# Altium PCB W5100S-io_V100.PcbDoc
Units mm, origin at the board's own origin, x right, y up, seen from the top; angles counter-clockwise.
Board outline 20 x 24 mm, 4 copper layers (Top Layer, Internal Plane 1, Internal Plane 2, Bottom Layer), stack 0.844 mm thick; 38 components, 31 nets, 160 pads, 49 vias.
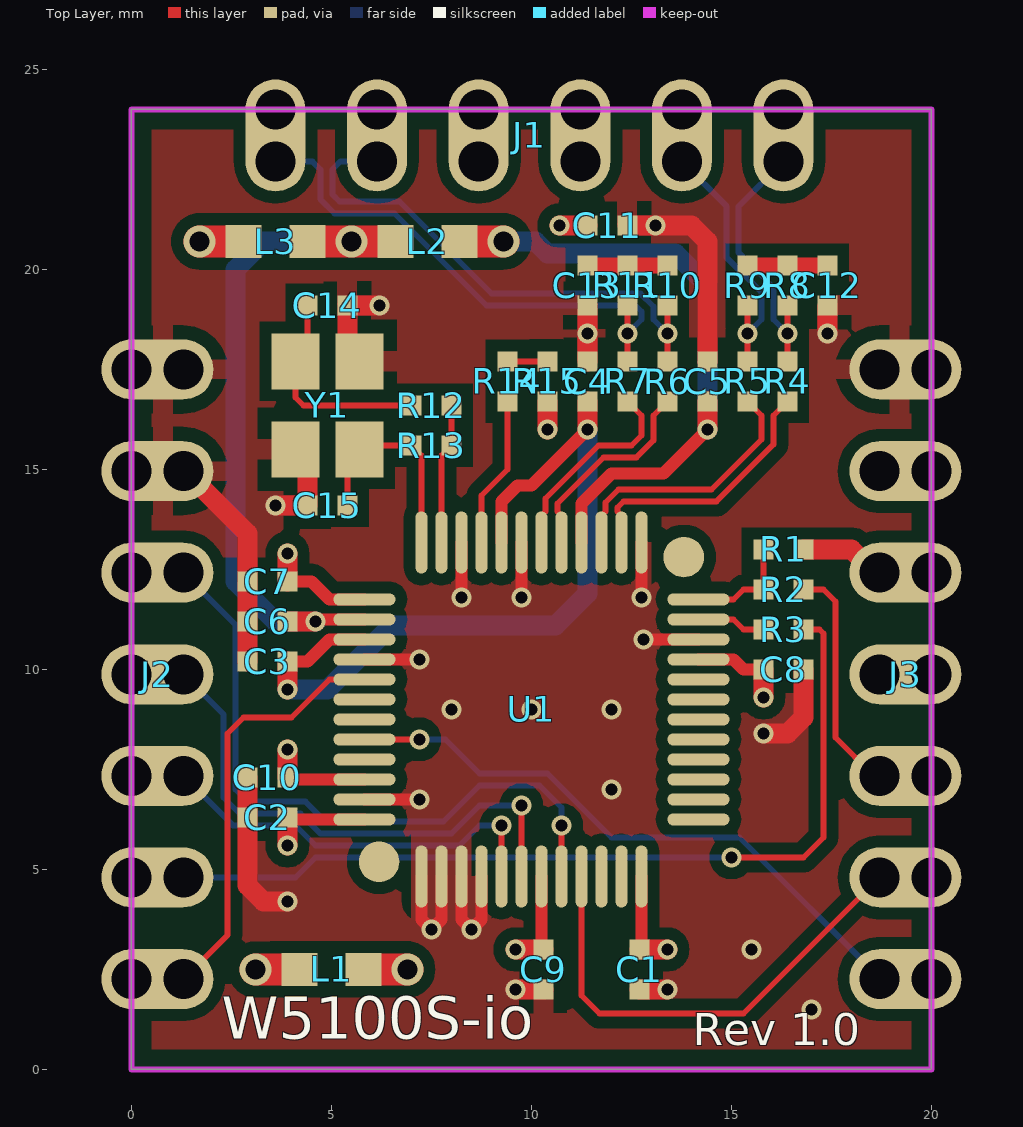
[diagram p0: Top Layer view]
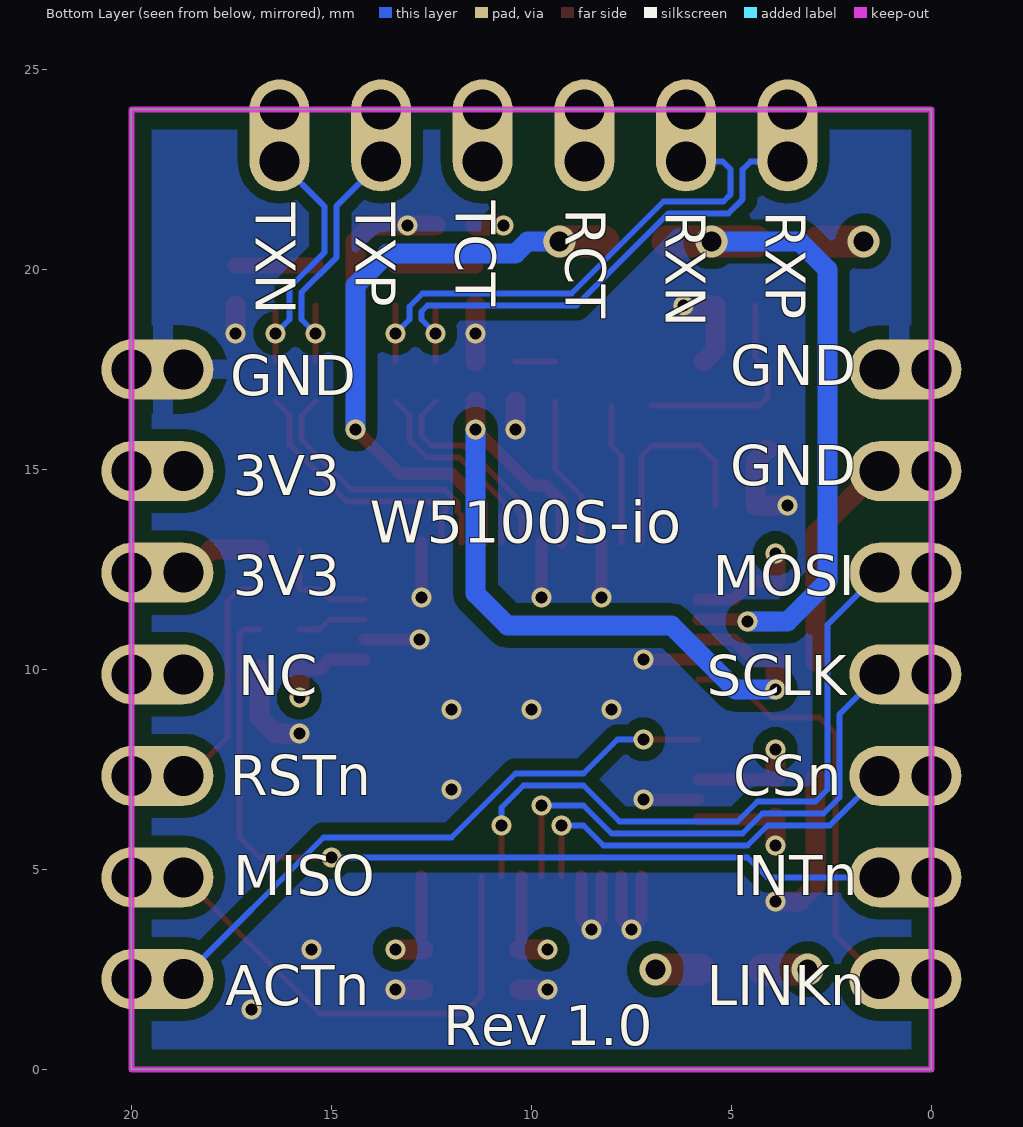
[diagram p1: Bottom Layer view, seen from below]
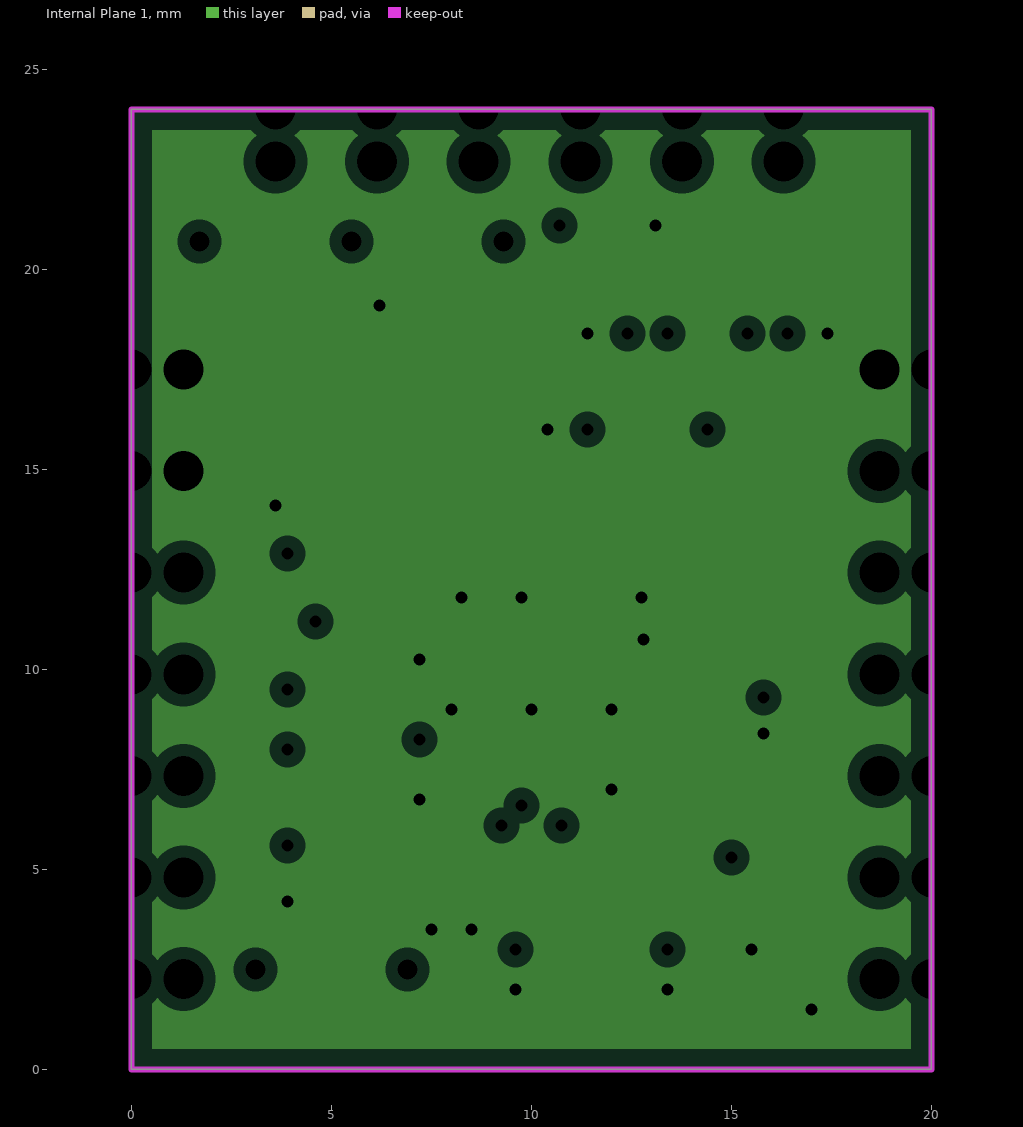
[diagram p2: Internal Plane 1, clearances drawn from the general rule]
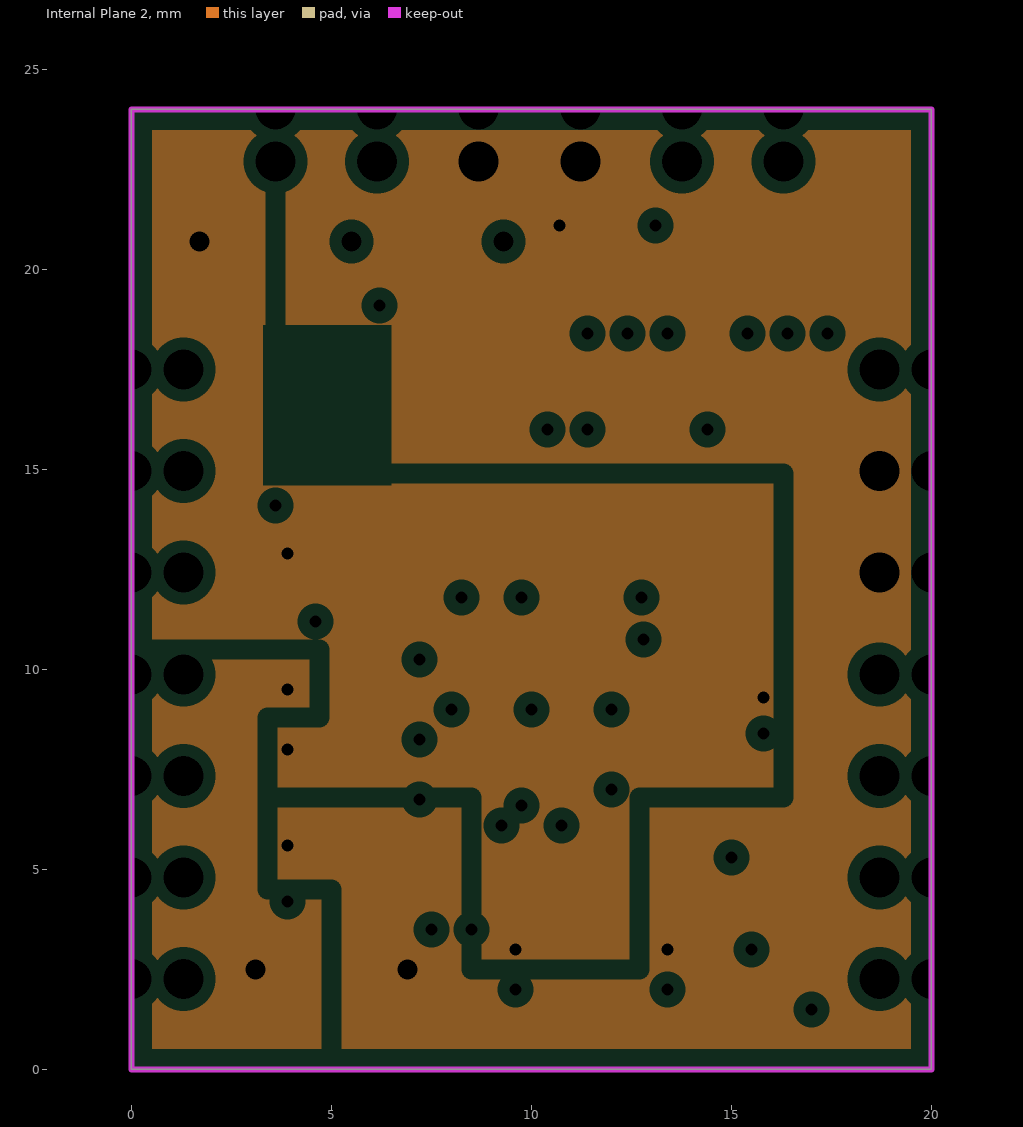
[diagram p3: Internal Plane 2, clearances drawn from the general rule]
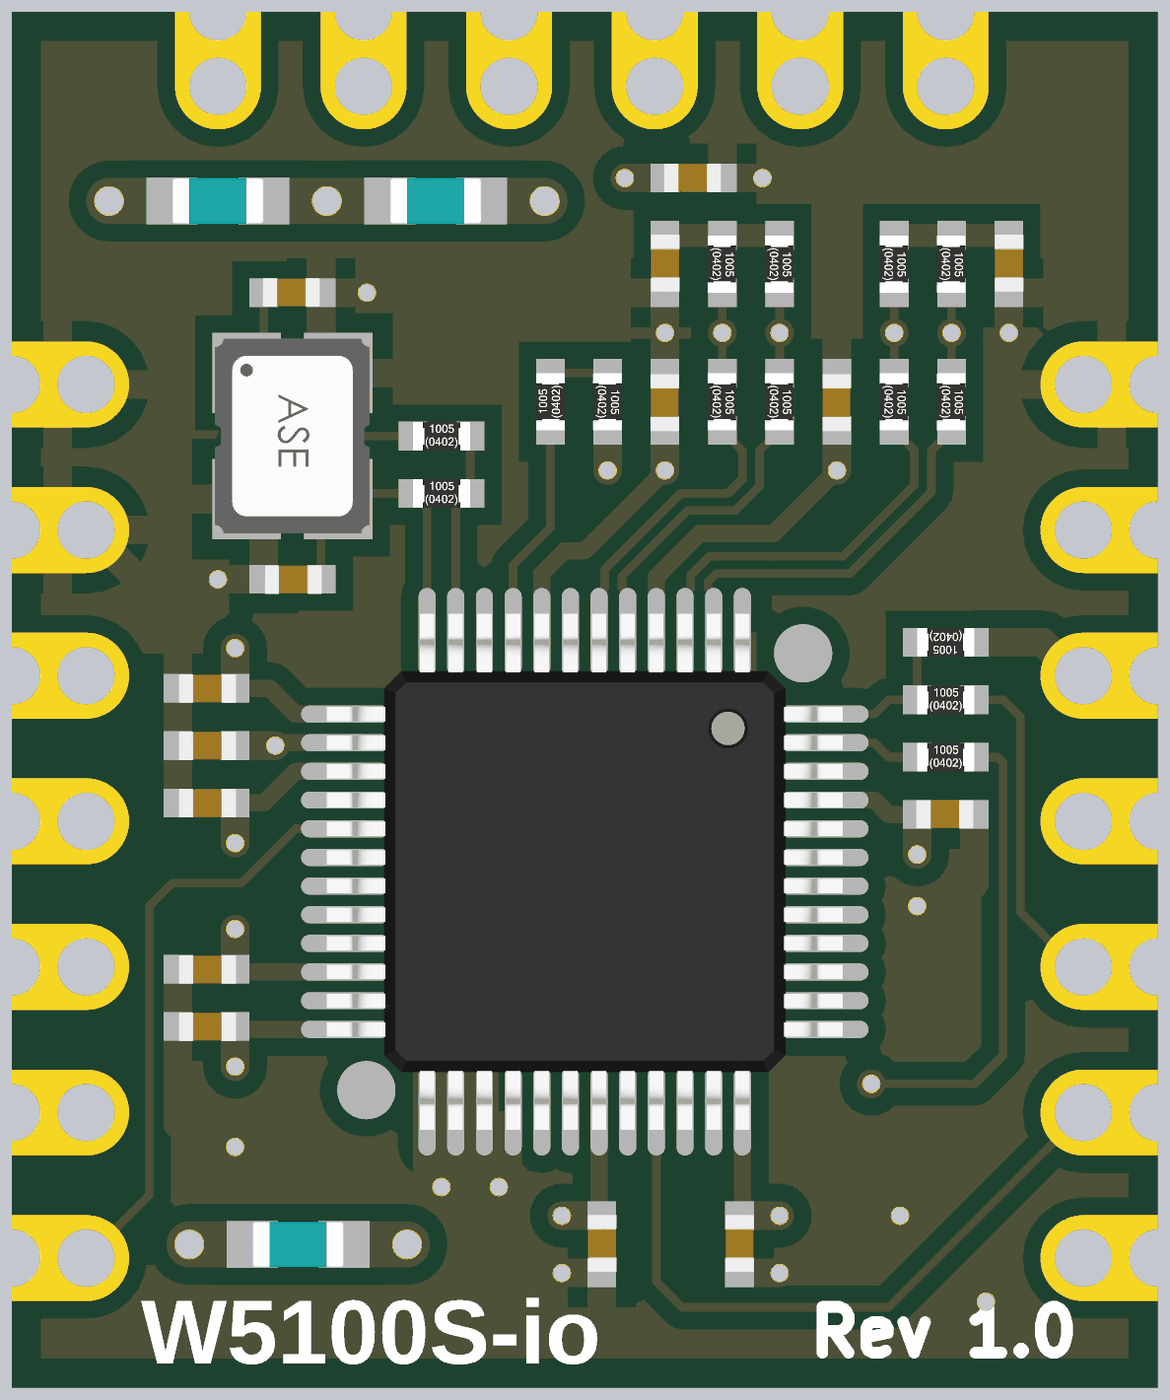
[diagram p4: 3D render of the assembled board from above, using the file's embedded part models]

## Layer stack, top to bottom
Top Solder: solder mask 0.0102, Solder Resist, Dk 3.5
Top Layer: signal copper 0.0356
Dielectric1: core 0.32, FR-4, Dk 4.8
Internal Plane 1: plane copper 0.0356, net GND
Dielectric 6: prepreg 0.127, Dk 4.2
Internal Plane 2: plane copper 0.036, net 3V3
Dielectric5: core 0.254, FR-4, Dk 4.2
Bottom Layer: signal copper 0.0356
Bottom Solder: solder mask 0.0102, Solder Resist, Dk 3.5

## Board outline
0,0 0,24 20,24 20,0

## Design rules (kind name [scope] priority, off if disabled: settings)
BoardOutlineClearance [All] p1: gap=0.5 ignorepadtopadclearanceinfootprint=FALSE
Clearance [All] p1: gap=0.15 ignorepadtopadclearanceinfootprint=FALSE except(0: Arc-Hole Track-Hole SMDPad-Hole THPad-Hole Via-Hole Fill-Hole Region-Hole Text-Hole; 0.3: Arc-Poly Track-Poly SMDPad-Poly THPad-Poly Via-Poly Fill-Poly Poly-Poly Poly-Region Poly-Text Poly-Hole)
DiffPairsRouting [All] p1: maxlimit=0.15 minlimit=0.15 mostfreqgap=0.15 toplayer_minwidth=0.15 toplayer_maxwidth=0.15 toplayer_prefwidth=0.15 bottomlayer_minwidth=0.15 bottomlayer_maxwidth=0.15 bottomlayer_prefwidth=0.15 maxuncoupledlength=15.24
HoleSize [All] p1: absolutevalues=TRUE maxlimit=4.064 minlimit=0.025 maxpercent=80.000 minpercent=20.000
PlaneClearance [All] p1: clearance=0.3
PlaneConnect [All] p1: planeconnectstyle=Direct reliefexpansion=0.508 reliefentries=4 reliefconductorwidth=0.254 reliefairgap=0.254
PolygonConnect [All] p1: thpad.connectstyle=Relief thpad.reliefconductorwidth=0.5 thpad.reliefentries=4 thpad.polygonreliefangle="90 Angle" thpad.airgapwidth=0.35 smdpad.connectstyle=Relief smdpad.reliefconductorwidth=0.5 smdpad.reliefentries=4 smdpad.polygonreliefangle="90 Angle" smdpad.airgapwidth=0.35 via.connectstyle=Direct via.reliefconductorwidth=0.254 via.reliefentries=4 via.polygonreliefangle="90 Angle" via.airgapwidth=0.254
RoutingVias [All] p1: holewidth=0.3 width=0.5 viastyle="Through Hole" minholewidth=0.3 minwidth=0.5 maxholewidth=0.5 maxwidth=0.8
SolderMaskExpansion [All] p1: expansion=0 istentingtop=FALSE
Width [All] p1: maxlimit=2.54 minlimit=0.102 preferedwidth=0.152
26 further rules are at their usual default settings.

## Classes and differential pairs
differential pair NewDifferentialPair4: +TX_N -TX_P
differential pair NewDifferentialPair3: +RX_N -RX_P
differential pair NewDifferentialPair2: +NetR5_2 -NetR4_2
differential pair NewDifferentialPair1: +NetR7_2 -NetR6_2

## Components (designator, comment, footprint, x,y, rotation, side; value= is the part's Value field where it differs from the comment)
C1 "0.1uF" CAP-0402 12.7,2.5 r90 top
C2 "0.1uF" CAP-0402 3.4,6.3 r0 top
C3 "0.1uF" CAP-0402 3.4,10.2 r0 top
C4 "0.1uF" CAP-0402 11.4,17.2 r270 top
C5 "0.1uF" CAP-0402 14.4,17.2 r270 top
C6 "1uF" CAP-0402 3.4,11.2 r0 top
C7 "0.1uF" CAP-0402 3.4,12.2 r0 top
C8 "0.1uF" CAP-0402 16.3,10 r180 top
C9 "0.1uF" CAP-0402 10.3,2.5 r90 top
C10 "0.1uF" CAP-0402 3.4,7.3 r0 top
C11 "0.1uF" CAP-0402 11.9,21.1 r180 top
C12 "0.1uF" CAP-0402 17.4,19.6 r90 top
C13 "0.1uF" CAP-0402 11.4,19.6 r90 top
C14 "18pF" CAP-0402 4.9,19.1 r180 top
C15 "18pF" CAP-0402 4.9,14.1 r0 top
J1 "2.54mm 1x6 Pin Header DIP" IDC-1X6(WI510IO) 16.3,22.7 r180 top
J2 "2.54mm 1x7 Pin Header DIP" IDC-1X7(WI510IO) 1.3,17.5 r270 top
J3 "2.54mm 1x7 Pin Header DIP" IDC-1X7(WI510IO) 20,17.5 r270 top
L1 "HH-1M1608-121JT" IND-0603 5,2.5 r180 top
L2 "HH-1M1608-121JT" IND-0603 7.4,20.7 r180 top
L3 "HH-1M1608-121JT" IND-0603 3.6,20.7 r180 top
R1 "4.7K" RES-0402 16.3,13 r180 top
R2 "0R" RES-0402 16.3,12 r0 top
R3 "0R" RES-0402 16.3,11 r0 top
R4 "3.3R" RES-0402 16.4,17.2 r270 top
R5 "3.3R" RES-0402 15.4,17.2 r270 top
R6 "3.3R" RES-0402 13.4,17.2 r270 top
R7 "3.3R" RES-0402 12.4,17.2 r270 top
R8 "49.9R" RES-0402 16.4,19.6 r270 top
R9 "49.9R" RES-0402 15.4,19.6 r270 top
R10 "49.9R" RES-0402 13.4,19.6 r270 top
R11 "49.9R" RES-0402 12.4,19.6 r270 top
R12 "0R" RES-0402 7.5,16.6 r0 top
R13 "1M" RES-0402 7.5,15.6 r0 top
R14 "12K/1%" RES-0402 9.4,17.2 r90 top
R15 "300R" RES-0402 10.4,17.2 r270 top
U1 "W5100S" LQFP48(0.5/9.0) 10,9 r270 top
Y1 "25MHz" OSC-82J0626 4.9,16.6 r270 top

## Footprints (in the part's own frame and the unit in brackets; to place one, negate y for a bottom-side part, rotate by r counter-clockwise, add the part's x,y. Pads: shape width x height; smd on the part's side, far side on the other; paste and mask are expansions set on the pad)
CAP-0402 [mm]
  rect 0.5x0.5 smd: 1(-0.5,0) 2(0.5,0)
  body extent -0.48,-0.25 0.52,0.25, height 0.6
IDC-1X6(WI510IO) [mm]
  oval 1.5x2.5 hole 1 copper offset 0,-0.5: 1(0,0) 2(2.54,0) 3(5.08,0) 4(7.62,0) 5(10.16,0) 6(12.7,0)
  oval 1.5x2.5 hole 1 copper offset 0,0.5: 1(0,-1.3) 2(2.54,-1.3) 3(5.08,-1.3) 4(7.62,-1.3) 5(10.16,-1.3) 6(12.7,-1.3)
IDC-1X7(WI510IO) [mm]
  oval 1.5x2.5 hole 1 copper offset 0,-0.5: 1(0,0) 2(2.54,0) 3(5.08,0) 4(7.62,0) 5(10.16,0) 6(12.7,0) 7(15.24,0)
  oval 1.5x2.5 hole 1 copper offset 0,0.5: 1(0,-1.3) 2(2.54,-1.3) 3(5.08,-1.3) 4(7.62,-1.3) 5(10.16,-1.3) 6(12.7,-1.3) 7(15.24,-1.3)
IND-0603 [mm] "Inductor 0603(1608)"
  rect 0.89x0.82 smd: 1(-0.8,0) 2(0.8,0)
  body extent -0.8,-0.4 0.8,0.4, height 0.95
LQFP48(0.5/9.0) [mm]
  round 1.016 smd: 0(-3.81,3.81) 0(3.81,-3.81)
  oval 1.55x0.3 smd: 1(-4.175,2.75) 2(-4.175,2.25) 3(-4.175,1.75) 4(-4.175,1.25) 5(-4.175,0.75) 6(-4.175,0.25) 7(-4.175,-0.25) 8(-4.175,-0.75) 9(-4.175,-1.25) 10(-4.175,-1.75) 11(-4.175,-2.25) 12(-4.175,-2.75) 25(4.175,-2.75) 26(4.175,-2.25) 27(4.175,-1.75) 28(4.175,-1.25) 29(4.175,-0.75) 30(4.175,-0.25) 31(4.175,0.25) 32(4.175,0.75) 33(4.175,1.25) 34(4.175,1.75) 35(4.175,2.25) 36(4.175,2.75)
  oval 0.3x1.55 smd: 13(-2.75,-4.175) 14(-2.25,-4.175) 15(-1.75,-4.175) 16(-1.25,-4.175) 17(-0.75,-4.175) 18(-0.25,-4.175) 19(0.25,-4.175) 20(0.75,-4.175) 21(1.25,-4.175) 22(1.75,-4.175) 23(2.25,-4.175) 24(2.75,-4.175) 37(2.75,4.175) 38(2.25,4.175) 39(1.75,4.175) 40(1.25,4.175) 41(0.75,4.175) 42(0.25,4.175) 43(-0.25,4.175) 44(-0.75,4.175) 45(-1.25,4.175) 46(-1.75,4.175) 47(-2.25,4.175) 48(-2.75,4.175)
  body extent -4.5,-4.5 4.5,4.5, height 1.5
OSC-82J0626 [mm]
  rect 1.4x1.2 smd: 1(-1.1,-0.8) 2(1.1,-0.8) 3(1.1,0.8) 4(-1.1,0.8)
  body extent -1.7,-1.35 1.7,1.35, height 1.06
RES-0402 [mm]
  rect 0.5x0.5 smd: 1(-0.5,0) 2(0.5,0)
  body extent -0.5,-0.25 0.5,0.25, height 0.35

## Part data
C1 C2 C3 C4 C5 C6 C7 C8 C9 C10 C11 C12 C13 C14 C15: library part CAP-0402, "Ceramic CAP 0402(1005)"
L1 L2 L3: library part IND-0603, "Inductor 0603(1608)"
R1 R2 R3 R4 R5 R6 R7 R8 R9 R10 R11 R12 R13 R14 R15: library part RES-0402, "RES-0402"
U1: "WIZnet Hardwired TCP/IP Chip"
Y1: library part OSC-82J0626-25MHz, "X-tal 25MHz,3.2x2.5 SMD, CL=18pF"

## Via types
v1: diameter 0.5, hole 0.3, Top Layer to Bottom Layer, tented both sides, 44 vias
v2: diameter 0.8, hole 0.5, Top Layer to Bottom Layer, tented both sides, 5 vias

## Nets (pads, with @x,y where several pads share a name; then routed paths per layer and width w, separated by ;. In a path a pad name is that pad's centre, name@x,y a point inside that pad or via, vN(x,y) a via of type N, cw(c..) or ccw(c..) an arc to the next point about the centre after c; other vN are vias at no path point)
1V2A: C5.2 L2.1 U1.4 | length 15.8
  Top Layer w0.3: U1.4 11.25,14.15 12,14.9 13.3,14.9 v1(14.4,16)
  Top Layer w0.5: v1(14.4,16) C5.2
  Top Layer w0.8: L2.1 v2(9.3,20.7)
  Bottom Layer w0.5: v2(9.3,20.7) 10.1,20.7 10.4,20.4 13.6,20.4 14.4,19.6 v1(14.4,16)
1V2D: C7.2 C8.2 C9.2 C10.2 L3.2 U1.13 U1.22 U1.31 U1.45 | length 11.5
  Top Layer w0.3: C10.2 3.95,7.25 U1.22 ; C7.2 4.5,12.2 4.95,11.75 U1.13 ; U1.31 10.25,3.05 C9.2 ; U1.45 15.05,10.25 15.3,10 C8.2
  Top Layer w0.5: C10.2 v1(3.9,8) ; C7.2 v1(3.9,12.9) ; v1(9.6,3) C9.2 ; v1(15.8,9.3) C8.2
  Top Layer w0.8: v2(1.7,20.7) L3.2
1V2O: C6.2 L2.2 L3.1 U1.14 | length 17.5
  Top Layer w0.3: v1(4.6,11.2) 4.65,11.25 U1.14
  Top Layer w0.5: C6.2 v1(4.6,11.2)
  Top Layer w0.8: L3.1 v2(5.5,20.7) L2.2
  Bottom Layer w0.5: v1(4.6,11.2) 3.6,11.2 2.6,12.2 2.6,20 3.3,20.7 v2(5.5,20.7)
3V3: C1.2 C2.2 C11.2 J1.3 J1.4 J3.2 J3.3 L1.1 R1.1 U1.24 U1.36 | length 10.4
  Top Layer w0.3: C2.2 3.95,6.25 U1.24 ; C1.2 12.75,3.05 U1.36
  Top Layer w0.5: v1(3.9,5.6) C2.2 ; v1(10.7,21.1) C11.2 ; C1.2 v1(13.4,3) ; R1.1 18,13 18.58,12.42 18.7,12.42 J3.3@20,12.42
  Top Layer w0.8: L1.1 v2(6.9,2.5)
3V3A: C3.2 C4.2 L1.2 U1.8 U1.15 | length 21.2
  Top Layer w0.3: C3.2 4.4,10.2 4.95,10.75 U1.15 ; U1.8 9.25,14.2 9.65,14.6 10,14.6 v1(11.4,16)
  Top Layer w0.5: v1(3.9,9.5) C3.2 ; v1(11.4,16) C4.2
  Top Layer w0.8: v2(3.1,2.5) L1.2
  Bottom Layer w0.5: v1(3.9,9.5) 4.9,9.5 6.5,11.1 10.6,11.1 11.4,11.9 v1(11.4,16)
ACTn: J3.7 U1.20 | length 16.7
  Top Layer w0.15: U1.20 v1(7.2,8.25)
  Bottom Layer w0.15: v1(7.2,8.25) 7.85,8.25 8.7,7.4 10.4,7.4 12,5.8 15.2,5.8 18.74,2.26 J3.7@20,2.26
CSn: J2.5 U1.29 | length 10.2
  Top Layer w0.15: U1.29 v1(9.25,6.1)
  Bottom Layer w0.15: J2.5@1.3,7.34 2.54,6.1 4.1,6.1 4.6,5.6 8.2,5.6 8.7,6.1 v1(9.25,6.1)
GND: C1.1 C2.1 C3.1 C4.1 C5.1 C6.1 C7.1 C8.1 C9.1 C10.1 C11.1 C12.1 C13.1 C14.1 C15.1 J2.1 J2.2 J3.1 R15.2 U1.1 U1.7 U1.10 U1.16 U1.23 U1.25 U1.26 U1.27 U1.28 U1.46 Y1.2 Y1.4 | length 41
  Top Layer w0.3: U1.23 v1(7.2,6.75) ; U1.16 v1(7.2,10.25) ; U1.25 7.25,3.75 v1(7.5,3.5) 7.75,3.75 U1.26 ; U1.27 8.25,3.75 v1(8.5,3.5) 8.75,3.75 U1.28 ; v1(8.25,11.8) U1.10 ; v1(9.75,11.8) U1.7 ; v1(12.75,11.8) U1.1 ; v1(12.8,10.75) U1.46
  Top Layer w0.5: J2.2@0,14.96 1.3,14.96 1.34,14.96 2.9,13.4 C7.1 C6.1 C3.1 ; C10.1 C2.1 2.9,4.6 3.3,4.2 v1(3.9,4.2) ; v1(3.6,14.1) C15.1 4.4,15.2 Y1.2 ; Y1.4 5.4,18 C14.1 v1(6.2,19.1) ; v1(9.6,2) C9.1 ; v1(10.4,16) R15.2 ; C4.1 v1(11.4,18.4) C13.1 ; C11.1 v1(13.1,21.1) 14,21.1 14.4,20.7 C5.1 ; C1.1 v1(13.4,2) ; v1(15.8,8.4) 16.4,8.4 16.8,8.8 C8.1 ; v1(17.4,18.4) C12.1
  other v1: 17,1.5 15.5,3 12,7 8,9 10,9 12,9
INTn: J2.6 R3.2 | length 23.4
  Top Layer w0.15: v1(15,5.3) 16.8,5.3 17.3,5.8 17.3,10.9 17.2,11 R3.2
  Bottom Layer w0.15: J2.6@0,4.8 1.3,4.8 4.1,4.8 4.6,5.3 v1(15,5.3)
LINKn: J2.7 U1.17 | length 10.6
  Top Layer w0.15: J2.7@1.3,2.26 2.4,3.36 2.4,8.4 2.8,8.8 4,8.8 4.95,9.75 U1.17
MISO: J3.6 U1.33 | length 12
  Top Layer w0.15: U1.33 11.25,1.85 11.7,1.4 15.3,1.4 J3.6@18.7,4.8
MOSI: J2.3 U1.32 | length 16.8
  Top Layer w0.15: U1.32 v1(10.75,6.1)
  Bottom Layer w0.15: J2.3@1.3,12.42 2.6,11.12 2.6,7 2.9,6.7 4.3,6.7 4.324,6.7 4.349,6.7 4.848,6.2 7.8,6.2 8.7,7.1 10.2,7.1 10.75,6.55 v1(10.75,6.1)
NetC12_2: C12.2 R8.1 R9.1 | length 2
  Top Layer w0.4: R9.1 R8.1 C12.2
NetC13_2: C13.2 R10.1 R11.1 | length 2
  Top Layer w0.4: C13.2 R11.1 R10.1
NetC14_2: C14.2 R12.1 Y1.1 | length 5.4
  Top Layer w0.15: C14.2 4.4,17.8 4.1,17.5 4.1,16.8 4.3,16.6 R12.1
NetC15_2: C15.2 R13.1 U1.12 Y1.3 | length 5.4
  Top Layer w0.15: C15.2 5.4,15.2 Y1.3 5.8,15.6 R13.1 7.25,15.35 U1.12
NetR1_2: R1.2 R2.1 U1.48 | length 2.7
  Top Layer w0.15: U1.48 15.05,11.75 15.3,12 R2.1 R1.2
NetR3_1: R3.1 U1.47 | length 1.7
  Top Layer w0.15: U1.47 15.05,11.25 15.3,11 R3.1
NetR4_2: R4.2 U1.2 | length 6.7
  Top Layer w0.15: U1.2 12.25,13.85 12.15,13.95 12.15,14.05 12.3,14.2 14.624,14.2 16.05,15.626 16.05,16.35 R4.2
NetR5_2: R5.2 U1.3 | length 6.7
  Top Layer w0.15: U1.3 11.75,13.85 11.85,13.95 11.85,14.174 12.176,14.5 14.5,14.5 15.75,15.75 15.75,16.35 R5.2
NetR6_2: R6.2 U1.5 | length 5.2
  Top Layer w0.15: U1.5 10.75,13.85 10.65,13.95 10.65,14.15 11.8,15.3 12.624,15.3 13.05,15.726 13.05,16.35 R6.2
NetR7_2: R7.2 U1.6 | length 5.2
  Top Layer w0.15: U1.6 10.25,13.85 10.35,13.95 10.35,14.274 11.676,15.6 12.5,15.6 12.75,15.85 12.75,16.35 R7.2
NetR12_2: R12.2 R13.2 U1.11 | length 3.5
  Top Layer w0.15: U1.11 7.75,15.35 R13.2 R12.2
NetR14_1: R14.1 U1.9 | length 3.8
  Top Layer w0.15: U1.9 8.75,14.35 9.4,15 R14.1
NetR14_2: R14.2 R15.1 | length 1
  Top Layer w0.15: R14.2 R15.1
RSTn: J3.5 R2.2 | length 7.1
  Top Layer w0.15: R2.2 17.3,12 17.6,11.7 17.6,8.3 18.56,7.34 18.7,7.34 J3.5@20,7.34
RX_N: J1.5 R6.1 R10.2 | length 13.2
  Top Layer w0.15: R6.1 v1(13.4,18.4) R10.2
  Bottom Layer w0.15: J1.5@6.14,22.7 5.22,22.7 5.02,22.5 5.02,21.88 5.2,21.7 6.7,21.7 9,19.4 12.724,19.4 13.05,19.074 13.05,18.75 v1(13.4,18.4)
RX_P: J1.6 R7.1 R11.2 | length 13.2
  Top Layer w0.15: R7.1 v1(12.4,18.4) R11.2
  Bottom Layer w0.15: J1.6@3.6,22.7 4.52,22.7 4.72,22.5 4.72,21.756 5.076,21.4 6.576,21.4 8.876,19.1 12.6,19.1 12.75,18.95 12.75,18.75 v1(12.4,18.4)
SCLK: J2.4 U1.30 | length 13.4
  Top Layer w0.15: U1.30 v1(9.75,6.6)
  Bottom Layer w0.15: J2.4@1.3,9.88 2.3,8.88 2.3,6.8 2.7,6.4 4.2,6.4 4.224,6.4 4.724,5.9 8,5.9 8.7,6.6 v1(9.75,6.6)
TX_N: J1.1 R4.1 R8.2 | length 6.7
  Top Layer w0.15: R4.1 v1(16.4,18.4) R8.2
  Bottom Layer w0.15: J1.1@16.3,22.7 15.18,21.58 15.18,20.42 16.05,19.55 16.05,18.75 v1(16.4,18.4)
TX_P: J1.2 R5.1 R9.2 | length 6.7
  Top Layer w0.15: R5.1 v1(15.4,18.4) R9.2
  Bottom Layer w0.15: J1.2@13.76,22.7 14.88,21.58 14.88,20.296 15.75,19.426 15.75,18.75 v1(15.4,18.4)
pads on no net: J3.4 U1.0 U1.18 U1.19 U1.21 U1.34 U1.35 U1.37 U1.38 U1.39 U1.40 U1.41 U1.42 U1.43 U1.44

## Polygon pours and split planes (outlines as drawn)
GND on Bottom Layer "NONET_L02_P-001" (solid, remove dead copper, pour order 1): -1,25 -1,-1 21,-1 21,25
GND on Top Layer "NONET_L02_P-001" (solid, remove dead copper, pour order 0): -1,-1 21,-1 21,25 -1,25 -1,21.5
3V3A on Internal Plane 2 (split plane): 4.448,9.052 3.4,9.052 3.335,9.044 3.274,9.018 3.222,8.978 3.182,8.926 3.156,8.865 3.148,8.8 3.148,4.5 3.156,4.435 3.182,4.374 3.222,4.322 3.274,4.282 3.335,4.256 3.4,4.248 4.748,4.248 4.748,0.51 0.51,0.51 0.51,10.248 4.448,10.248
3V3 on Internal Plane 2 (split plane): 19.49,0.51 5.252,0.51 5.252,4.5 5.244,4.565 5.218,4.626 5.178,4.678 5.126,4.718 5.065,4.744 5,4.752 3.652,4.752 3.652,6.548 8.248,6.548 8.248,2.5 8.256,2.435 8.282,2.374 8.322,2.322 8.374,2.282 8.435,2.256 8.5,2.248 12.7,2.248 12.765,2.256 12.826,2.282 12.878,2.322 12.918,2.374 12.944,2.435 12.952,2.5 12.952,6.548 16.3,6.548 16.365,6.556 16.426,6.582 16.478,6.622 16.518,6.674 16.544,6.735 16.552,6.8 16.552,14.9 16.544,14.965 16.518,15.026 16.478,15.078 16.426,15.118 16.365,15.144 16.3,15.152 6.5,15.152 6.5,18.6 3.852,18.6 3.852,23.49 19.49,23.49
1V2D on Internal Plane 2 (split plane): 3.348,18.6 3.3,18.6 3.3,14.6 6.5,14.6 6.5,14.648 16.048,14.648 16.048,7.052 12.7,7.052 12.635,7.044 12.574,7.018 12.522,6.978 12.482,6.926 12.456,6.865 12.448,6.8 12.448,2.752 8.752,2.752 8.752,6.8 8.744,6.865 8.718,6.926 8.678,6.978 8.626,7.018 8.565,7.044 8.5,7.052 3.652,7.052 3.652,8.548 4.7,8.548 4.765,8.556 4.826,8.582 4.878,8.622 4.918,8.674 4.944,8.735 4.952,8.8 4.952,10.5 4.944,10.565 4.918,10.626 4.878,10.678 4.826,10.718 4.765,10.744 4.7,10.752 0.51,10.752 0.51,23.49 3.348,23.49
GND on Internal Plane 1 (split plane): 19.49,0.51 0.51,0.51 0.51,23.49 19.49,23.49

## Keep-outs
Keep-Out Layer:
  the board outline again, w0.15
  text ".Layer_Name" at 9.398,44.45 h1.52

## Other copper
Top Layer:
  text ".Layer_Name" at 9.398,44.45 h1.52
Bottom Layer:
  text ".Layer_Name" at 9.398,44.45 h1.52
Internal Plane 1 (plane layer: these items are gaps in the copper):
  text ".Layer_Name" at 9.398,44.45 h1.52
Internal Plane 2 (plane layer: these items are gaps in the copper):
  rectangle: 3.3,14.6 6.5,18.6
  lines w0.5: 0,10.5 4.7,10.5 4.7,8.8 3.4,8.8 3.4,4.5 5,4.5 5,0 ; 3.4,6.8 8.5,6.8 8.5,2.5 12.7,2.5 12.7,6.8 16.3,6.8 16.3,14.9 3.6,14.9 3.6,24
  text ".Layer_Name" at 9.398,44.45 h1.52

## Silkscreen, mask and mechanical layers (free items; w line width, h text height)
Top Overlay:
  text ".Layer_Name" at 9.398,44.482 h1.52
  text "Rev 1.0" at 14.037,0.6 h0.8
  text "W5100S-io" at 2.259,0.421 h1.8
Bottom Overlay:
  text ".Layer_Name" at 9.398,44.45 h1.52
  text "TCT" at 11.896,21.724 h1 r90
  text "TXP" at 14.396,21.671 h1 r90
  text "TXN" at 16.896,21.671 h1 r90
  text "RCT" at 9.146,21.526 h1 r90
  text "RXP" at 4.146,21.474 h1 r90
  text "RXN" at 6.646,21.474 h1 r90
  text "GND" at 5.026,17.104 h1
  text "GND" at 17.526,16.854 h1
  text "GND" at 5.026,14.604 h1
  text "3V3" at 17.474,14.354 h1
  text "W5100S-io" at 14.041,12.821 h1.8
  text "MOSI" at 5.466,11.854 h1
  text "3V3" at 17.474,11.854 h1
  text "SCLK" at 5.616,9.354 h1
  text "NC" at 17.328,9.354 h1
  text "CSn" at 4.955,6.854 h1
  text "RSTn" at 17.545,6.854 h1
  text "INTn" at 4.981,4.354 h1
  text "MISO" at 17.454,4.354 h1
  text "LINKn" at 5.623,1.604 h1
  text "ACTn" at 17.65,1.604 h1
  text "Rev 1.0" at 12.204,0.604 h1
Top Paste:
  text ".Layer_Name" at 9.398,44.45 h1.52
Bottom Paste:
  text ".Layer_Name" at 9.398,44.45 h1.52
Top Solder:
  text ".Layer_Name" at 9.398,44.45 h1.52
Bottom Solder:
  text ".Layer_Name" at 9.398,44.45 h1.52
Drill Guide:
  text ".Layer_Name" at 9.398,44.45 h1.52
Mechanical 2:
  lines w0.127: 34.846,16.129 61.008,16.129 ; 34.846,18.923 61.008,18.923 ; 33.5,4.775 ccw(c34.211,4.775) 34.211,4.064 61.389,4.064 ccw(c61.389,4.775) 62.1,4.775 62.1,24.003 ccw(c61.389,24.003) 61.389,24.714 34.211,24.714 ccw(c34.211,24.003) 33.5,24.003 33.5,4.775
  lines w0.15: 0,0 0,24 20,24 20,0 0,0
  text "BOARD NAME : W5100S-io" at 0,55.626 h1.52
  text "VERSION : V100" at 0,52.832 h1.52
  text "SIZE : 20mmX24mmX1.0T" at 0,50.038 h1.52
  text "GERBER DATE : 2022.06.28" at 0,47.244 h1.52
  text "LAYER :" at 0,44.45 h1.52
  text "Layer Stack Up Detail for:" at 34.973,22.606 h1.02
  text "W5100S-io_V100.PcbDoc" at 34.846,20.193 h1.27
  text "Layer Name : 4L  1.0T" at 34.973,17.018 h1.02
  text "Top Layer" at 34.846,13.335 h1.52
  text "Internal Plane 1 (GND)" at 34.846,10.541 h1.52
  text "Internal Plane 2 (POWER)" at 34.846,7.874 h1.52
  text "Bottom Layer" at 34.846,5.334 h1.52
  text "KS Technology artwork" at 33.5,0 h5.08
Drill Drawing:
  text ".Layer_Name" at 9.398,44.45 h1.52
  text ".Legend" at 35.532,27.432 h1.02

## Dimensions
0,0 to 0,24 on Mechanical 2
0,0 to 20,0 on Mechanical 2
